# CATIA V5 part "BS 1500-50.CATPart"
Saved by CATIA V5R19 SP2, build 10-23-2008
Part number: BS 1500-50
Bounding box of the stored display mesh (mm): x -31.459 to 31.459, y -31.459 to 31.459, z 0 to 144
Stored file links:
  C:\Users\Bora\Desktop\3D Katı model\BS serisi\BS 1500\BS 1500-50.CATPart
  C:\Program Files\Dassault Systemes\B19\intel_a\reffiles\standard\MetricThickPitch.txt
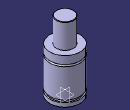
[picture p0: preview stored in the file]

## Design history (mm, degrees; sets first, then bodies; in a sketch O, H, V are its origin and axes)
Body1 (main body)
  Sketch1 on yz-plane, origin (0, 0, 0), H (0, 1, 0), V (0, 0, 1)
    point P1 (31.5, 77)
    point P2 (31.5, 73)
    point P3 (31.5, 77)
    point P7 (18, 143)
    point P9 (18, 143)
    point P14 (31.5, 73)
    arc A1 centre (31.5, 75) radius 2 from (31.5, 77) to (31.5, 73) ccw
    line L1 (31.5, 77) -> (31.5, 93)
    line L2 (31.5, 0) -> (31.5, 8)
    arc A2 centre (17, 143) radius 1 from (18, 143) to (17, 144) ccw
    line L3 (18, 143) -> (18, 93)
    line L4 (29, 13) -> (29, 8)
    line L5 (31.5, 13) -> (31.5, 73)
    line L6 (17, 144) -> (0, 144)
    point P15 (0, 144)
    line L7 (18, 93) -> (31.5, 93)
    line L8 (0, 0) -> (31.5, 0)
    line L9 (29, 13) -> (31.5, 13)
    line L10 (29, 8) -> (31.5, 8)
    coincidence: P15 V, P1 P3, P2 P14, P7 P9
    tangency: L6 A2
    horizontal: L7 H, L8 H, L9 H, L10 H
  Shaft1: profile Sketch1, axis Sketch1.V, angle 360
  Sketch2 on face of Shaft1 from Sketch1.L8, origin (0, 0, 0), H (1, 0, 0), V (0, -1, 0)
    point P1 (10, 0)
    distance P1 V = 10
  Hole1: placed by Sketch2, at (10, 0, 0) direction (0, 0, 1), diameter 6.647, depth 5, threaded "M8", thread diameter 8, thread depth 5, pitch 1.25
  CircPattern1: of Hole1, instances 2, angular step 180, axis from xy-plane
